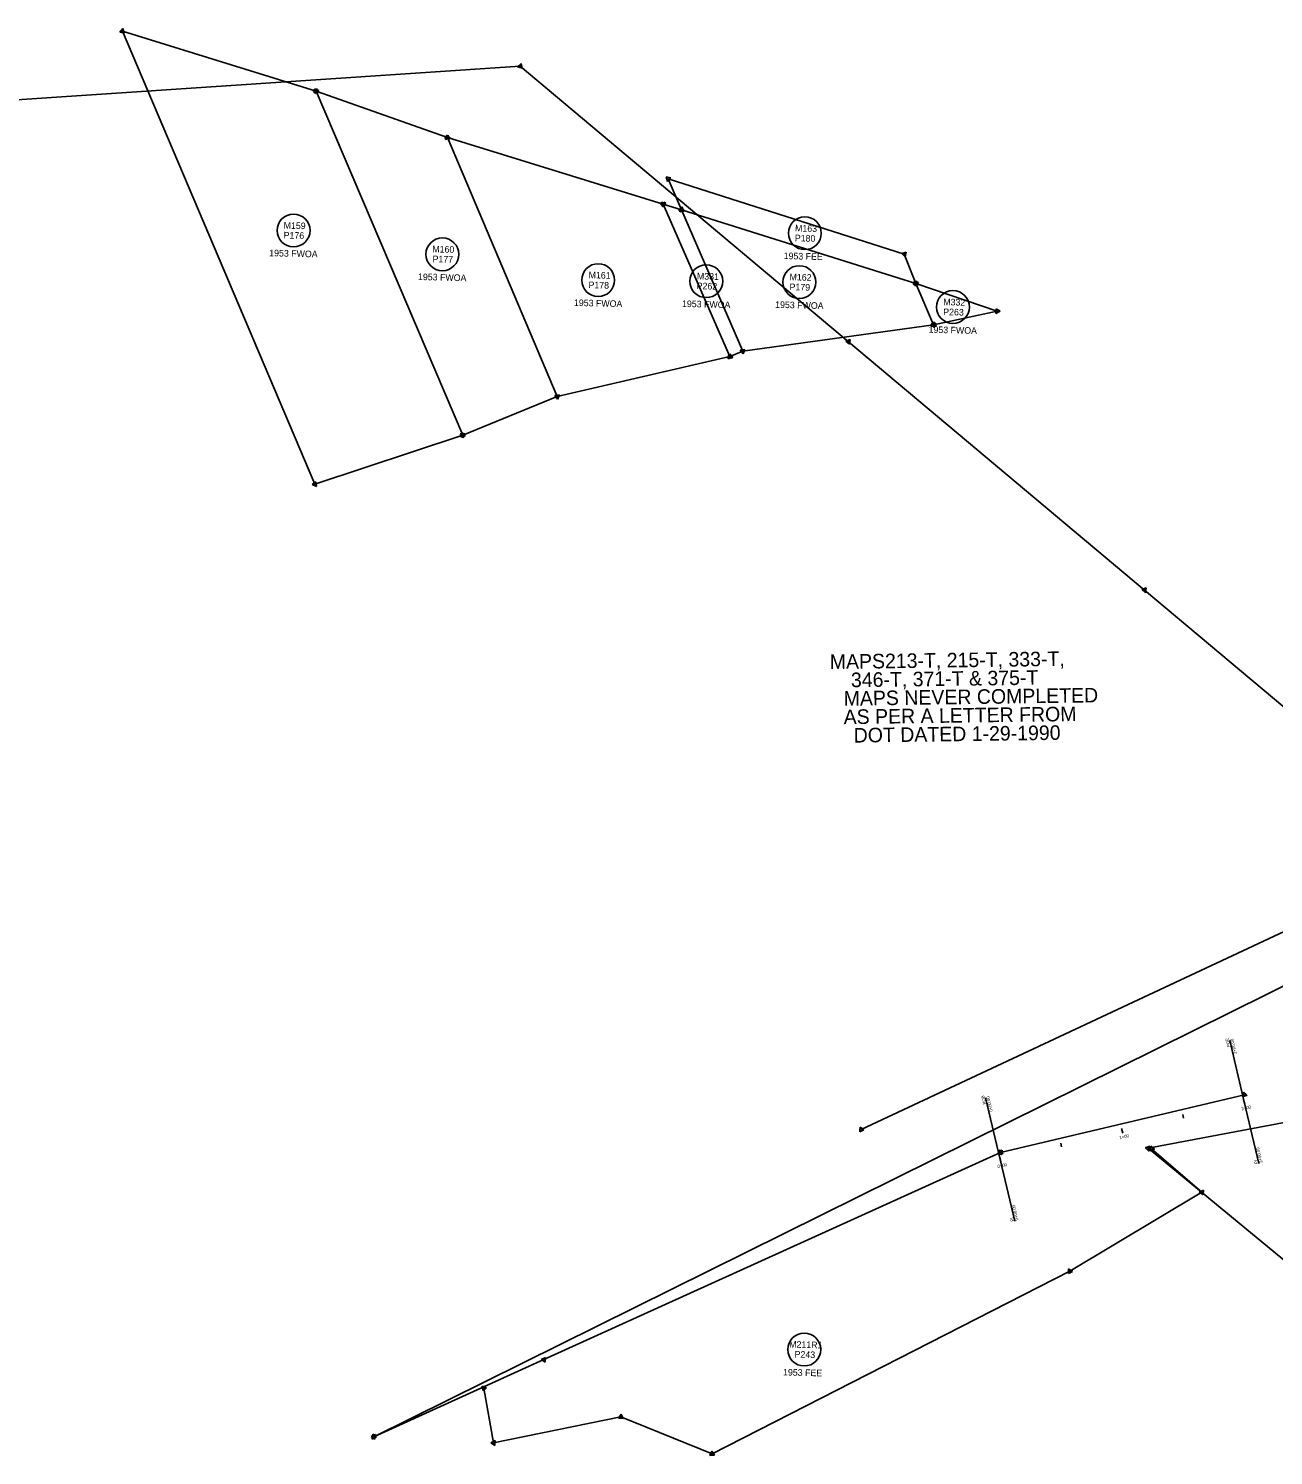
# Model space of a CAD drawing. Extents: x 325018 to 414989, y 1517547 to 1550415.
# Drawn here: x 362506 to 363499, y 1523820 to 1524959 of the extents above; entities that cross this region are included whole.
import ezdxf

# ---------------------------------------------------------------- set-up
doc = ezdxf.new("R2010")
doc.units = 0
for name, color, linetype in [('ACSC_P_T', 7, 'Continuous'), ('ACSCT_P', 7, 'Continuous'), ('ACSR_P_T', 7, 'Continuous'), ('ACSRT_P', 7, 'Continuous'), ('ADEFAULT', 7, 'Continuous'), ('LAM_I', 7, 'Continuous'), ('Level 56', 7, 'Continuous'), ('MHB', 7, 'Continuous'), ('MHBWOA', 7, 'Continuous'), ('MRBL1', 7, 'Continuous'), ('MRBL2', 7, 'Continuous'), ('XDEFAULT_P', 7, 'Continuous')]:
    doc.layers.add(name, color=color, linetype=linetype)

msp = doc.modelspace()

# ---------------------------------------------------------------- linework, layer by layer
at = {"layer": 'ACSCT_P'}
for points in [[(363475.5, 1524101.9), (363463.9, 1524151)], [(363280.8, 1524056), (363269.2, 1524105.1)], [(363475.5, 1524101.9), (363487, 1524052.9)], [(363280.8, 1524056), (363292.4, 1524006.9)]]:
    msp.add_lwpolyline(points, dxfattribs=at)
at = {"layer": 'ACSRT_P'}
for points in [[(363475, 1524103.8), (363475.9, 1524100.1)], [(363426.5, 1524091.8), (363427.1, 1524089)], [(363377.7, 1524080.8), (363378.6, 1524077.1)], [(363329.1, 1524068.9), (363329.8, 1524066.1)], [(363280.4, 1524057.9), (363281.2, 1524054.1)]]:
    msp.add_lwpolyline(points, dxfattribs=at)
at = {"layer": 'ADEFAULT'}
for points in [[(363396.7, 1524065.2), (363400.2, 1524066.5)], [(363399.6, 1524062.8), (363396.7, 1524065.2)], [(363396.8, 1524065.6), (363400.5, 1524066.3)], [(363399.3, 1524062.7), (363396.8, 1524065.6)], [(363400.5, 1524066.3), (363399.3, 1524062.7)], [(363400.2, 1524066.5), (363399.6, 1524062.8)]]:
    msp.add_lwpolyline(points, dxfattribs=at)
for centre in [(363398.9, 1524064.9), (363398.8, 1524064.9)]:
    msp.add_circle(centre, 1.09, dxfattribs=at)
at = {"layer": 'Level 56'}
for centre in [(362717.1, 1524797.4), (363125, 1524795.2), (362835.8, 1524778.4), (362960.1, 1524757.8), (363046.3, 1524756.9), (363120.6, 1524756.2), (363243.1, 1524736.3), (363124.5, 1523904.3)]:
    msp.add_circle(centre, 13.1, dxfattribs=at)
at = {"layer": 'MHB'}
for p, q in [((363026.6, 1524814), (363015.9, 1524838.6)), ((363015.9, 1524838.6), (363204.3, 1524778.4)), ((363204.3, 1524778.4), (363213.4, 1524755)), ((363169.9, 1524079.9), (363546.7, 1524256.5)), ((363572, 1524097.9), (363398.9, 1524064.9)), ((363398.9, 1524064.9), (363533.6, 1523953.7)), ((363441.7, 1524029.8), (363401.6, 1524064.5)), ((363336.4, 1523966.8), (363441.7, 1524029.8)), ((363050.9, 1523821), (363336.4, 1523966.8)), ((362868.9, 1523873.5), (362876.7, 1523829.8)), ((362876.7, 1523829.8), (362978.2, 1523850.6)), ((362978.2, 1523850.6), (363050.9, 1523821))]:
    msp.add_line(p, q, dxfattribs=at)
for points in [[(363015.5, 1524836.5), (363014.3, 1524840.1)], [(363014.3, 1524840.1), (363018, 1524839.3)], [(363018, 1524839.3), (363015.5, 1524836.5)], [(363024.6, 1524813.1), (363026.8, 1524816.2)], [(363026.8, 1524816.2), (363028.3, 1524812.7)], [(363028.3, 1524812.7), (363024.6, 1524813.1)], [(363202.2, 1524778.9), (363205.8, 1524780)], [(363204.9, 1524776.3), (363202.2, 1524778.9)], [(363205.8, 1524780), (363204.9, 1524776.3)], [(363211.7, 1524756.4), (363215.5, 1524755.8)], [(363213.1, 1524752.9), (363211.7, 1524756.4)], [(363215.5, 1524755.8), (363213.1, 1524752.9)], [(363168.7, 1524078.1), (363169, 1524081.8)], [(363172.1, 1524079.7), (363168.7, 1524078.1)], [(363169, 1524081.8), (363172.1, 1524079.7)], [(363400.2, 1524062.8), (363400.9, 1524066.5)], [(363400.9, 1524066.5), (363403.8, 1524064.1)], [(363403.8, 1524064.1), (363400.2, 1524062.8)], [(363439.5, 1524030), (363443, 1524031.6)], [(363443, 1524031.6), (363442.6, 1524027.8)], [(363442.6, 1524027.8), (363439.5, 1524030)], [(363335.3, 1523964.9), (363335.3, 1523968.7)], [(363335.3, 1523968.7), (363338.6, 1523966.7)], [(363338.6, 1523966.7), (363335.3, 1523964.9)], [(362867.5, 1523875.1), (362871.1, 1523873.8)], [(362868.2, 1523871.4), (362867.5, 1523875.1)], [(362871.1, 1523873.8), (362868.2, 1523871.4)], [(362976.2, 1523849.6), (362978.4, 1523852.7)], [(362979.9, 1523849.3), (362976.2, 1523849.6)], [(362978.4, 1523852.7), (362979.9, 1523849.3)], [(362874.5, 1523829.9), (362877.9, 1523831.6)], [(362877.6, 1523827.8), (362874.5, 1523829.9)], [(362877.9, 1523831.6), (362877.6, 1523827.8)], [(363049.1, 1523819.8), (363050.8, 1523823.1)], [(363052.8, 1523819.9), (363049.1, 1523819.8)], [(363050.8, 1523823.1), (363052.8, 1523819.9)]]:
    msp.add_lwpolyline(points, dxfattribs=at)
for centre, radius in [((363015.9, 1524838.6), 0.227), ((363026.6, 1524814), 1.09), ((363204.3, 1524778.4), 0.227), ((363213.4, 1524755), 1.09), ((363169.9, 1524079.9), 1.09), ((363401.6, 1524064.5), 1.09), ((363441.7, 1524029.8), 0.227), ((363336.4, 1523966.8), 0.227), ((362868.9, 1523873.5), 1.09), ((362978.2, 1523850.6), 0.227), ((362876.7, 1523829.8), 0.227), ((363050.9, 1523821), 0.227)]:
    msp.add_circle(centre, radius, dxfattribs=at)
at = {"layer": 'MHBWOA'}
for p, q in [((362735.1, 1524908.6), (362580.6, 1524956.4)), ((362580.6, 1524956.4), (362734.1, 1524594.9)), ((362839.8, 1524871.6), (362735.1, 1524908.6)), ((362852, 1524634.1), (362735.1, 1524908.6)), ((362839.8, 1524871.6), (363012, 1524818.4)), ((362927.4, 1524664.8), (362839.8, 1524871.6)), ((363026.6, 1524814), (363012, 1524818.4)), ((363012, 1524818.4), (363065.2, 1524696.7)), ((363026.6, 1524814), (363213.4, 1524755)), ((363075.5, 1524701.1), (363026.6, 1524814)), ((363213.4, 1524755), (363278.5, 1524733)), ((363213.4, 1524755), (363227.7, 1524722.2)), ((363278.5, 1524733), (363227.7, 1524722.2)), ((363227.7, 1524722.2), (363075.5, 1524701.1)), ((363065.2, 1524696.7), (362927.4, 1524664.8)), ((363065.2, 1524696.7), (363075.5, 1524701.1)), ((362852, 1524634.1), (362927.4, 1524664.8)), ((362734.1, 1524594.9), (362852, 1524634.1))]:
    msp.add_line(p, q, dxfattribs=at)
for points in [[(362578.5, 1524955.8), (362581, 1524958.6)], [(362582.2, 1524955), (362578.5, 1524955.8)], [(362581, 1524958.6), (362582.2, 1524955)], [(362733.1, 1524907.8), (362735.4, 1524910.8)], [(362736.8, 1524907.3), (362733.1, 1524907.8)], [(362734.5, 1524906.6), (362733.6, 1524910.2)], [(362733.6, 1524910.2), (362737.2, 1524909.1)], [(362734.4, 1524906.6), (362733.7, 1524910.3)], [(362733.7, 1524910.3), (362737.2, 1524909)], [(362737.2, 1524909), (362734.4, 1524906.6)], [(362737.2, 1524909.1), (362734.5, 1524906.6)], [(362735.4, 1524910.8), (362736.8, 1524907.3)], [(362837.7, 1524871.1), (362840.5, 1524873.6)], [(362838.3, 1524870), (362839.2, 1524873.6)], [(362839.2, 1524873.6), (362841.9, 1524871.1)], [(362840.5, 1524873.6), (362841.3, 1524870)], [(362841.3, 1524870), (362837.7, 1524871.1)], [(362841.9, 1524871.1), (362838.3, 1524870)], [(363009.9, 1524818.8), (363013.5, 1524820)], [(363012.7, 1524816.3), (363009.9, 1524818.8)], [(363011.4, 1524816.3), (363010.5, 1524820)], [(363010.5, 1524820), (363014.1, 1524818.9)], [(363014.1, 1524818.9), (363011.4, 1524816.3)], [(363013.5, 1524820), (363012.7, 1524816.3)], [(363024.5, 1524813.5), (363027.2, 1524816.1)], [(363025.1, 1524812.4), (363025.9, 1524816.1)], [(363025.9, 1524816.1), (363028.7, 1524813.6)], [(363027.2, 1524816.1), (363028.1, 1524812.4)], [(363028.1, 1524812.4), (363024.5, 1524813.5)], [(363028.7, 1524813.6), (363025.1, 1524812.4)], [(363211.3, 1524754.6), (363214.1, 1524757.1)], [(363211.3, 1524755.5), (363214.9, 1524756.7)], [(363214.1, 1524753), (363211.3, 1524755.5)], [(363214.9, 1524753.4), (363211.3, 1524754.6)], [(363214.1, 1524757.1), (363214.9, 1524753.4)], [(363214.9, 1524756.7), (363214.1, 1524753)], [(363277.3, 1524731.2), (363277.5, 1524735)], [(363280.7, 1524732.9), (363277.3, 1524731.2)], [(363277.5, 1524735), (363280.7, 1524732.9)], [(363225.6, 1524722.9), (363229.3, 1524723.7)], [(363228.1, 1524720.1), (363225.6, 1524722.9)], [(363225.8, 1524721.1), (363227.6, 1524724.4)], [(363229.6, 1524721.1), (363225.8, 1524721.1)], [(363227.6, 1524724.4), (363229.6, 1524721.1)], [(363229.3, 1524723.7), (363228.1, 1524720.1)], [(363073.4, 1524702), (363077.2, 1524702.5)], [(363073.4, 1524701.9), (363077.2, 1524702.5)], [(363077.2, 1524702.5), (363075.8, 1524699)], [(363077.2, 1524702.5), (363075.8, 1524699)], [(363063.4, 1524695.5), (363065.1, 1524698.9)], [(363067.2, 1524695.7), (363063.4, 1524695.5)], [(363063.9, 1524694.9), (363064.3, 1524698.7)], [(363067.4, 1524696.4), (363063.9, 1524694.9)], [(363064.3, 1524698.7), (363067.4, 1524696.4)], [(363065.1, 1524698.9), (363067.2, 1524695.7)], [(363075.8, 1524699), (363073.4, 1524702)], [(363075.8, 1524699), (363073.4, 1524701.9)], [(362925.4, 1524665.5), (362929, 1524666.3)], [(362925.4, 1524665.6), (362929.2, 1524666.1)], [(362927.7, 1524662.7), (362925.4, 1524665.6)], [(362927.9, 1524662.7), (362925.4, 1524665.5)], [(362929.2, 1524666.1), (362927.7, 1524662.7)], [(362929, 1524666.3), (362927.9, 1524662.7)], [(362850.1, 1524635), (362853.8, 1524635.4)], [(362852.3, 1524631.9), (362850.1, 1524635)], [(362850.7, 1524632.4), (362851.2, 1524636.1)], [(362851.2, 1524636.1), (362854.2, 1524633.8)], [(362853.8, 1524635.4), (362852.3, 1524631.9)], [(362854.2, 1524633.8), (362850.7, 1524632.4)], [(362731.9, 1524594.7), (362734.9, 1524596.9)], [(362735.3, 1524593.1), (362731.9, 1524594.7)], [(362734.9, 1524596.9), (362735.3, 1524593.1)]]:
    msp.add_lwpolyline(points, dxfattribs=at)
for centre, radius in [((362580.6, 1524956.4), 0.227), ((362735.1, 1524908.6), 1.09), ((362735.1, 1524908.6), 1.09), ((362735.1, 1524908.6), 1.09), ((362839.8, 1524871.6), 1.09), ((362839.8, 1524871.6), 0.227), ((363012, 1524818.4), 1.09), ((363012, 1524818.4), 0.227), ((363026.6, 1524814), 1.09), ((363026.6, 1524814), 0.227), ((363213.4, 1524755), 1.09), ((363213.4, 1524755), 0.227), ((363278.5, 1524733), 0.227), ((363227.7, 1524722.2), 1.09), ((363227.7, 1524722.2), 0.227), ((363075.5, 1524701.1), 1.09), ((363065.2, 1524696.7), 1.09), ((363065.2, 1524696.7), 0.227), ((363075.5, 1524701.1), 0.227), ((362927.4, 1524664.8), 1.09), ((362927.4, 1524664.8), 0.227), ((362852, 1524634.1), 1.09), ((362852, 1524634.1), 0.227), ((362734.1, 1524594.9), 0.227)]:
    msp.add_circle(centre, radius, dxfattribs=at)
at = {"layer": 'MRBL1'}
for p, q in [((362781.1, 1523834.7), (363673.8, 1524277.1)), ((363281, 1524061.6), (363475.6, 1524107.7))]:
    msp.add_line(p, q, dxfattribs=at)
for points in [[(363474, 1524106.2), (363475.1, 1524109.8)], [(363477.7, 1524107.1), (363474, 1524106.2)], [(363475.1, 1524109.8), (363477.7, 1524107.1)], [(363279.4, 1524060.1), (363280.5, 1524063.7)], [(363283.1, 1524060.9), (363279.4, 1524060.1)], [(363280.5, 1524063.7), (363283.1, 1524060.9)], [(362779.9, 1523832.9), (362780.2, 1523836.7)], [(362783.3, 1523834.6), (362779.9, 1523832.9)], [(362780.2, 1523836.7), (362783.3, 1523834.6)]]:
    msp.add_lwpolyline(points, dxfattribs=at)
for centre in [(363475.6, 1524107.7), (363281, 1524061.6), (362781.1, 1523834.7)]:
    msp.add_circle(centre, 1.09, dxfattribs=at)
at = {"layer": 'MRBL2'}
for p, q in [((361993.9, 1524868.1), (362897.9, 1524928.6)), ((362897.9, 1524928.6), (363159.8, 1524708.6)), ((363159.8, 1524708.6), (363395.9, 1524510.4)), ((363395.9, 1524510.4), (363673.8, 1524277.1)), ((363281, 1524061.6), (362916.8, 1523896.3)), ((362916.8, 1523896.3), (362781.1, 1523834.7))]:
    msp.add_line(p, q, dxfattribs=at)
for points in [[(362895.8, 1524928.1), (362898.6, 1524930.6)], [(362898.6, 1524930.6), (362899.4, 1524926.9)], [(362899.4, 1524926.9), (362895.8, 1524928.1)], [(363157.7, 1524709), (363161.2, 1524710.3)], [(363160.6, 1524706.6), (363157.7, 1524709)], [(363161.2, 1524710.3), (363160.6, 1524706.6)], [(363393.8, 1524510.8), (363397.3, 1524512.1)], [(363396.7, 1524508.3), (363393.8, 1524510.8)], [(363397.3, 1524512.1), (363396.7, 1524508.3)], [(363278.9, 1524061.8), (363282.3, 1524063.3)], [(363281.9, 1524059.6), (363278.9, 1524061.8)], [(363282.3, 1524063.3), (363281.9, 1524059.6)], [(362914.6, 1523896.5), (362918.1, 1523898)], [(362917.7, 1523894.3), (362914.6, 1523896.5)], [(362918.1, 1523898), (362917.7, 1523894.3)], [(362779, 1523834.9), (362782.4, 1523836.5)], [(362782, 1523832.7), (362779, 1523834.9)], [(362782.4, 1523836.5), (362782, 1523832.7)]]:
    msp.add_lwpolyline(points, dxfattribs=at)
for centre, radius in [((362897.9, 1524928.6), 0.227), ((363159.8, 1524708.6), 0.227), ((363395.9, 1524510.4), 0.227), ((363281, 1524061.6), 1.09), ((362916.8, 1523896.3), 0.227), ((362781.1, 1523834.7), 1.09)]:
    msp.add_circle(centre, radius, dxfattribs=at)
at = {"layer": 'XDEFAULT_P'}
for points in [[(363474, 1524106.2), (363475.1, 1524109.8)], [(363477.7, 1524107.1), (363474, 1524106.2)], [(363475.1, 1524109.8), (363477.7, 1524107.1)], [(363279.4, 1524060.1), (363280.5, 1524063.7)], [(363283.1, 1524060.9), (363279.4, 1524060.1)], [(363280.5, 1524063.7), (363283.1, 1524060.9)]]:
    msp.add_lwpolyline(points, dxfattribs=at)
for centre in [(363475.6, 1524107.7), (363281, 1524061.6)]:
    msp.add_circle(centre, 1.09, dxfattribs=at)

# ---------------------------------------------------------------- texts
at = {"layer": 'ACSC_P_T'}
for s, p in [('POE', (363464.4, 1524146.1)), ('2+00.00', (363469.6, 1524140.4)), ('POB', (363269.7, 1524100.2)), ('0+00.00', (363274.9, 1524094.4)), ('2+00.00', (363490.1, 1524053.6)), ('PI', (363486.4, 1524052.7)), ('0+00.00', (363295.4, 1524007.7)), ('PI', (363291.8, 1524006.8))]:
    msp.add_text(s, height=2.5, rotation=103.2751, dxfattribs=at).set_placement(p)
at = {"layer": 'ACSR_P_T'}
for s, p in [('2+00', (363473.5, 1524095.1)), ('1+00', (363376.2, 1524072.1)), ('0+00', (363278.9, 1524049.1))]:
    msp.add_text(s, height=2.5, rotation=13.2751, dxfattribs=at).set_placement(p)
at = {"layer": 'LAM_I'}
for s, p in [('MAPS213-T, 215-T, 333-T,', (363144.9, 1524447.4)), ('346-T, 371-T & 375-T', (363161.8, 1524432.9)), ('MAPS NEVER COMPLETED', (363156, 1524418.1)), ('AS PER A LETTER FROM', (363156, 1524403.4)), ('DOT DATED 1-29-1990', (363164, 1524388.7))]:
    msp.add_text(s, height=11.626, rotation=0.7697, dxfattribs=at).set_placement(p)
at = {"layer": 'Level 56'}
for s, p in [('M159', (362709.1, 1524798.9)), ('P176', (362709.1, 1524791.1)), ('P180', (363116.9, 1524788.8)), ('M163', (363117.1, 1524796.7)), ('1953 FWOA', (362697.6, 1524776.9)), ('M160', (362827.7, 1524780)), ('P177', (362827.9, 1524772.1)), ('1953 FEE', (363108, 1524774.6)), ('1953 FWOA', (362816.3, 1524757.9)), ('M161', (362952.4, 1524759.3)), ('M331', (363038.8, 1524758.4)), ('M162', (363112.7, 1524757.7)), ('P178', (362952.3, 1524751.4)), ('P262', (363038.6, 1524750.6)), ('P179', (363112.7, 1524749.8)), ('1953 FWOA', (362940.7, 1524737.2)), ('1953 FWOA', (363026.9, 1524736.4)), ('1953 FWOA', (363101.2, 1524735.7)), ('M332', (363235.3, 1524737.8)), ('P263', (363235.3, 1524729.9)), ('1953 FWOA', (363223.6, 1524715.8)), ('M211R1', (363112.4, 1523905.9)), ('P243', (363116.7, 1523897.9)), ('1953 FEE', (363107.5, 1523883.7))]:
    msp.add_text(s, height=5.25, rotation=358.5141, dxfattribs=at).set_placement(p)

doc.saveas('drawing.dxf')
